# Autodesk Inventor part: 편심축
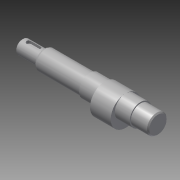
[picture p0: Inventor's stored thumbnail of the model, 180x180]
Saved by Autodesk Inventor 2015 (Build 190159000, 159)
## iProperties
Created: 2017-08
Part Number: 편심축
Material: 강철, 연강
Document SubType Name: Modeling
Designer: mduedu
Density: 1 g/cm^3
Appearance: 강철
Author: mduedu
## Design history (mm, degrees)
sketch "스케치1"
  geometry: L1 (0, 0)-(118, 0); L2 (118, 0)-(118, 8.5); L3 (118, 8.5)-(103, 8.5); L4 (103, 8.5)-(103, 9.5); L5 (103, 9.5)-(59, 9.5); L6 (59, 9.5)-(59, 8.5); L7 (59, 8.5)-(19, 8.5); L8 (19, 8.5)-(19, 6); L9 (19, 6)-(0, 6); L10 (0, 6)-(0, 0)
  constraints: 20 end point, 6 parallel, 2 collinear, 2 perpendicular, 1 horizontal
  dimensions: "d0" = 118 distance of L1.start L1.end; "d1" = 17 diameter of L3 L1; "d2" = 19 diameter of L5 L1; "d3" = 12 diameter of L9 L1; "d4" = 19 distance of L8.end L9.end; "d5" = 15 distance of L2.end L3.end; "d6" = 44 distance of L4.end L5.end
revolve "회전1" sketch "스케치1" stored, may be unused: angle "d7" = 90 deg
node "작업 평면1"
sketch "스케치2"
  geometry: C1 r 9.5 at (0, 0) reference; C2 r 13 at (0, -3.5); 1 further point
  constraints: 1 centre point, 1 tangent, 1 vertical alignment
  dimensions: "d8" = 3.5 distance of point (0, 0) C2.centre
extrude "돌출1" join sketch "스케치2" stored distance "d9" = 18; taper "d10" = 0 deg
chamfer "모따기1" distance "d11" = 1; stored, may be unused: second distance "d12" = 2, angle "d13" = 45 deg
node "작업 평면2"
sketch "스케치3"
  geometry: L1 (3.5, -2)-(-4.5, -2); L2 (-4.5, -2)-(-4.5, 2); L3 (-4.5, 2)-(3.5, 2); L4 (3.5, 2)-(3.5, -2); L5 (9.5, 6)-(9.5, -6) reference; A1 r 2 centre (3.5, 0) between (3.5, -2) and (3.5, 2); A2 r 2 centre (-4.5, 0) between (-4.5, 2) and (-4.5, -2); A3 r 2 centre (3.5, 0) between (3.5, 2) and (3.5, -2); A4 r 2 centre (-4.5, 0) between (-4.5, -2) and (-4.5, 2); 1 further point
  constraints: 8 end point, 8 point on circle, 4 centre point, 2 midpoint, 2 parallel, 1 horizontal, 1 horizontal alignment, 1 perpendicular
  dimensions: "d14" = 12 dimension on A2 A1; "d16" = 4 distance between parallel lines of L3 L1; "d17" = 4 distance edge to line of A1 L5
extrude "돌출2" cut sketch "스케치3" distance "d18" = 2.5; taper "d19" = 0 deg
chamfer "모따기2" distance "d20" = 1; stored, may be unused: second distance "d21" = 2, angle "d22" = 45 deg
chamfer "모따기3" distance "d23" = 1; stored, may be unused: second distance "d24" = 2, angle "d25" = 60 deg
fillet "모깎기1" dims "d26" = 0.5
hole "구멍1" diameter "d29" = 3.242; stored, may be unused: countersink angle "d33" = 90 deg, drill point angle "d35" = 118 deg; dims "d30" = 8, "d31" = 4, "d32" = 2, "d34" = 10, "d36" = 10, "d37" = 10
node "솔리드1"
node "절단 모서리 투영1"
